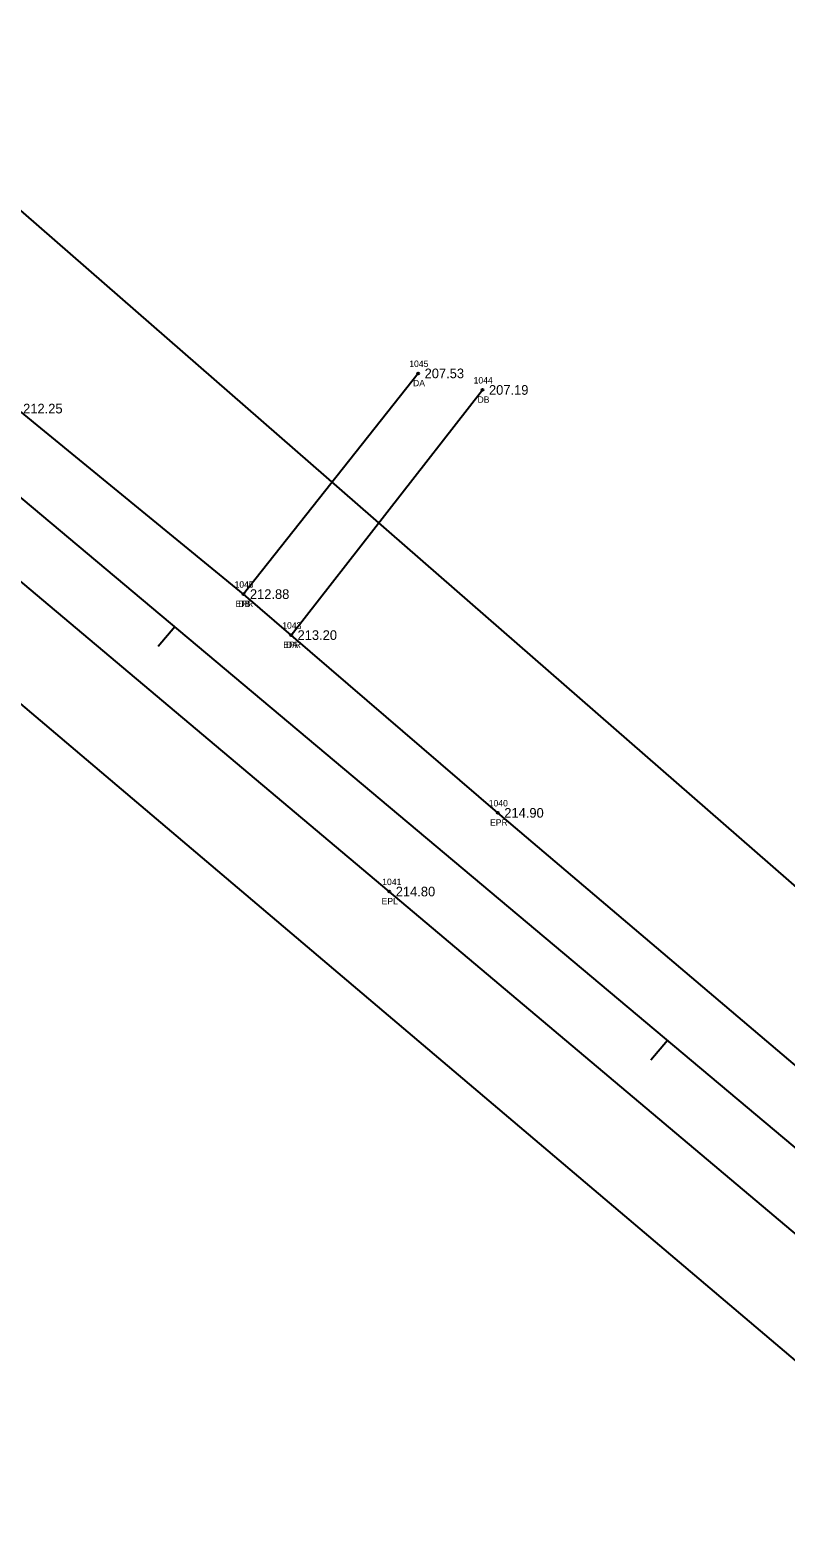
# Model space of a CAD drawing. Extents: x 2259948 to 2261336, y 1064647 to 1065986.
# Drawn here: x 2260900.1 to 2261017.7, y 1064842.1 to 1065076.4 of the extents above; entities that cross this region are included whole.
import ezdxf

# ---------------------------------------------------------------- set-up
doc = ezdxf.new("R2010")
doc.units = 0
for name, color, linetype in [('RD_EX_Driveway', 7, 'Continuous'), ('RD_EX_Driveway_txCode', 7, 'Continuous'), ('RD_EX_Road', 7, 'Continuous'), ('RD_EX_Road_txCode', 7, 'Continuous'), ('RD_EX_TX_Driveway_ELEV', 7, 'Continuous'), ('RD_EX_TX_Road_ELEV', 7, 'Continuous'), ('RD_EX_VEG', 7, 'Continuous'), ('RD_HC_Cl', 7, 'Continuous'), ('RD_HC_Data_Tic', 7, 'Continuous'), ('RD_SMD_Locator', 7, 'Continuous')]:
    doc.layers.add(name, color=color, linetype=linetype)

msp = doc.modelspace()

# ---------------------------------------------------------------- linework, layer by layer
at = {"layer": 'RD_EX_Driveway'}
for p, q in [((2260960.5, 1065023.07), (2260933.33, 1064988.76)), ((2260940.74, 1064982.39), (2260970.51, 1065020.5))]:
    msp.add_line(p, q, dxfattribs=at)
at = {"layer": 'RD_EX_Road'}
for points in [[(2261124.91, 1064827.37), (2261072.16, 1064871.6), (2261053.72, 1064886.47), (2261045.58, 1064893.1), (2260972.89, 1064954.76), (2260940.74, 1064982.39), (2260933.33, 1064988.76), (2260898.06, 1065017.6), (2260832.89, 1065075.07)], [(2261112.68, 1064810.86), (2261032.95, 1064877.72), (2260956.01, 1064942.53), (2260884.53, 1065002.6), (2260818.6, 1065058.26)]]:
    msp.add_lwpolyline(points, dxfattribs=at)
at = {"layer": 'RD_EX_VEG'}
for points in [[(2261134.31, 1064842.95), (2260842.2, 1065097.67), (2260806.91, 1065126.77), (2260758.4, 1065156.57), (2260401.57, 1065481.47), (2260414.95, 1065532.7)], [(2261105.29, 1064796.67), (2260883, 1064984.96), (2260766.14, 1065062.68), (2260367.33, 1065416.28), (2260257.33, 1065527.76)]]:
    msp.add_lwpolyline(points, dxfattribs=at)
at = {"layer": 'RD_HC_Cl'}
msp.add_line((2261118.79, 1064819.11), (2260589.55, 1065263.13), dxfattribs=at)
at = {"layer": 'RD_HC_Data_Tic'}
for p, q in [((2260922.65, 1064983.67), (2260920.08, 1064980.6)), ((2260999.26, 1064919.4), (2260996.69, 1064916.33))]:
    msp.add_line(p, q, dxfattribs=at)
at = {"layer": 'RD_SMD_Locator'}
for centre in [(2260960.5, 1065023.07), (2260970.51, 1065020.5), (2260933.33, 1064988.76), (2260933.33, 1064988.76), (2260940.74, 1064982.39), (2260940.74, 1064982.39), (2260972.89, 1064954.76), (2260956.01, 1064942.53)]:
    msp.add_circle(centre, 0.15, dxfattribs=at)

# ---------------------------------------------------------------- texts
at = {"layer": 'RD_EX_Driveway_txCode'}
for s, p in [('1045', (2260959.11, 1065024.07)), ('DA', (2260959.7, 1065021.07)), ('1044', (2260969.12, 1065021.5)), ('DB', (2260969.73, 1065018.5)), ('1046', (2260931.92, 1064989.76)), ('DB', (2260932.55, 1064986.76)), ('1043', (2260939.36, 1064983.39)), ('DA', (2260939.95, 1064980.39))]:
    msp.add_text(s, height=1, dxfattribs=at).set_placement(p)
at = {"layer": 'RD_EX_Road_txCode'}
for s, p in [('1047', (2260931.95, 1064989.76)), ('EPR', (2260932.11, 1064986.76)), ('1042', (2260939.36, 1064983.39)), ('EPR', (2260939.52, 1064980.39)), ('1040', (2260971.47, 1064955.76)), ('EPR', (2260971.67, 1064952.76)), ('1041', (2260954.91, 1064943.53)), ('EPL', (2260954.81, 1064940.53))]:
    msp.add_text(s, height=1, dxfattribs=at).set_placement(p)
at = {"layer": 'RD_EX_TX_Driveway_ELEV'}
for s, p in [('207.53', (2260961.5, 1065022.32)), ('207.19', (2260971.51, 1065019.75)), ('212.88', (2260934.33, 1064988.01)), ('213.20', (2260941.74, 1064981.64))]:
    msp.add_text(s, height=1.5, dxfattribs=at).set_placement(p)
at = {"layer": 'RD_EX_TX_Road_ELEV'}
for s, p in [('212.25', (2260899.06, 1065016.85)), ('212.88', (2260934.33, 1064988.01)), ('213.20', (2260941.74, 1064981.64)), ('214.90', (2260973.89, 1064954.01)), ('214.80', (2260957.01, 1064941.78))]:
    msp.add_text(s, height=1.5, dxfattribs=at).set_placement(p)

doc.saveas('drawing.dxf')
